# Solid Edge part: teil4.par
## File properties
Author: Susi
Template: Normal.par
Last saved by: Susi
Revision: 1
Application: Solid Edge
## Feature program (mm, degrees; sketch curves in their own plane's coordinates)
sketch for "unnamed Protrusion 1" plane through (0, 0, 0) normal (0, 0, 1) x-axis (1, 0, 0)
extrude "unnamed Protrusion 1" add finite 10 along +normal
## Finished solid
Body 1: solid body, 6 faces, 12 edges, 8 vertices.
  Faces by surface: plane 6
  Edges by curve: line 12
Bounding box of the edges (mm): 10.000 x 25.000 x 10.000, from (-7.2, -19.4667, 0) to (2.8, 5.5333, 10).
Planar faces by outward normal: +x 1, +y 1, +z 1, -x 1, -y 1, -z 1
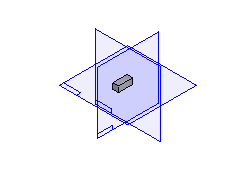
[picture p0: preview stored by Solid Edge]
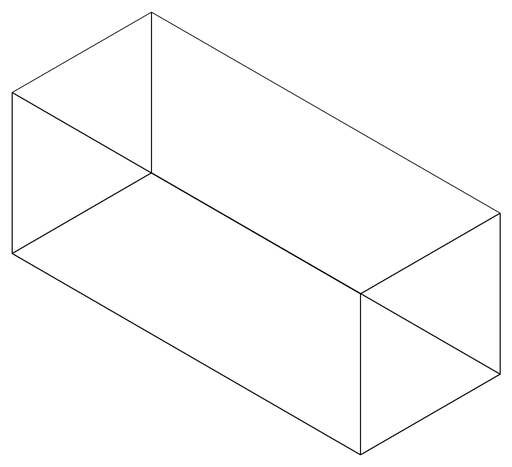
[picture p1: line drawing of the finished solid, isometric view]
